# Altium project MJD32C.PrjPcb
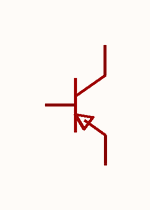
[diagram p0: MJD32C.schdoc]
1 sheet, 1 parts. Net scope: global (net labels, ports and power ports of the same name join across sheets).

## Sheet MJD32C.schdoc
size 127 x 101 mm

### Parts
Q?  mjd32c  [TO-252-3_L6.5-W5.8-P4.58-BL]  (value not drawn)

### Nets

Not connected (* = marked no-connect by the designer): Q? 1(B) 2(C) 3(E)

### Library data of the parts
Q? = mjd32c: 晶体管类型:PNP;集电极电流(Ic):3A;集射极击穿电压(Vceo):100V;耗散功率(Pd):1.25W;直流电流增益(hFE):15;; Manufacturer: CJ(江苏长电/长晶); AddInBom: yes; ModelId: b30bfce30d0f4a429b5e4d5ada8cad65; ModelTransform: 249.9995,380.57715,0,0,0,0,0,38.779,0; type: PNP; Current - Collector(Ic): 3A; Collector - Emitter Voltage VCEO: 100V; Pd - Power Dissipation: 1.25W; DC Current Gain: 15; Transition frequency(fT): 3MHz; Current - Collector Cutoff: 50uA; Vce Saturation(VCE(sat)): 1.2V; Emitter-Base Voltage(Vebo): 5V; Number: 1个PNP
